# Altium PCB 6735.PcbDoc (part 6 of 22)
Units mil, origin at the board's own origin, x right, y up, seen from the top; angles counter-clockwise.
Board outline 2641.73 x 5165.35 mil, 6 copper layers (Top, Inner Layer 2, Inner Layer 3, Inner Layer 4, Inner Layer 5, Bottom), stack 35.7 mil thick; 1011 components, 790 nets, 4118 pads, 9325 vias.
Unrouted connection lines stored in the file: 4610.
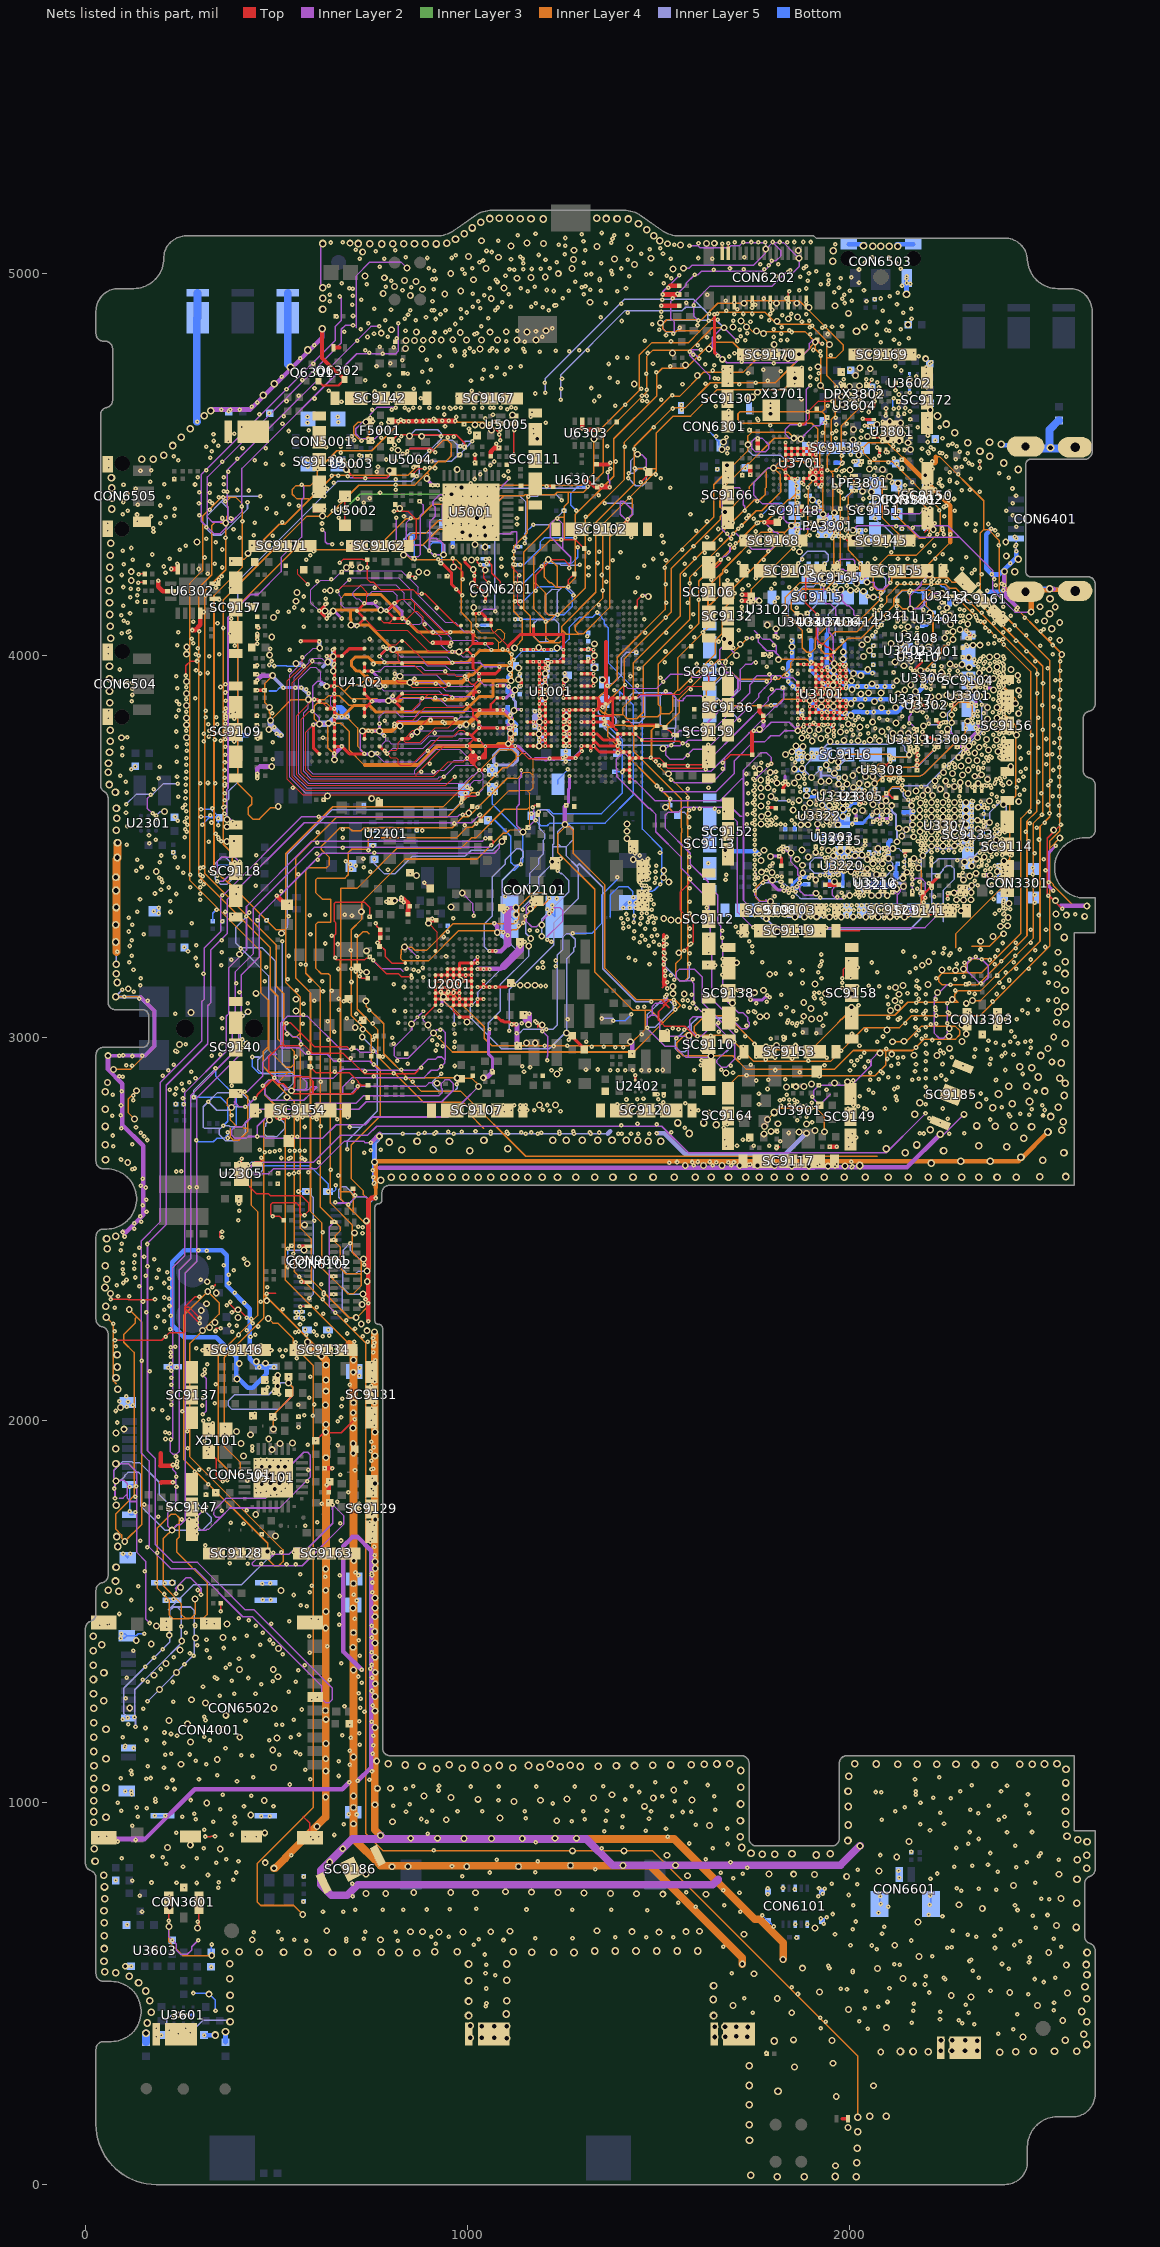
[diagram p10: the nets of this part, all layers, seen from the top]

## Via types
v1: diameter 12, hole 4, Top to Inner Layer 2, 3329 vias
v2: diameter 12, hole 4, Inner Layer 5 to Bottom, 3071 vias
v3: diameter 18, hole 10, Inner Layer 2 to Inner Layer 5, 1928 vias
v4: diameter 10, hole 4, Top to Inner Layer 2, 525 vias
v5: diameter 20, hole 12, Top to Bottom, 472 vias

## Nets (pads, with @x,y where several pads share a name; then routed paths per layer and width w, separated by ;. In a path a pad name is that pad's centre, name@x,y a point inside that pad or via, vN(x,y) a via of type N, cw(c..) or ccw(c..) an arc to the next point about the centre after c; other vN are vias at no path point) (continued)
D_GND: (continued)
  Top w4: v1(34.95,910.49) CON4001.14@36.94,912.47 ; v1(36.95,1463.49) 39.09,1465.62 CON4001.13@48.04,1465.62 ; CON4001.14@48.04,912.48 CON4001.14@36.94,912.47 ; CON4001.13@48.04,1470.55 CON4001.13@48.04,1465.63 ; v1(55.95,911.49) 54.96,912.47 CON4001.14@36.94,912.47 ; v1(56.95,1464.49) CON4001.13@55.81,1465.62 ; v1(58.63,4327.23) 58.63,4331.92 CON6505.4@58.9,4332.18 v1(58.9,4346.5) ; v1(59.33,3836.28) 59.33,3840.02 CON6504.4@58.9,3840.44 58.9,3854.01 v1(60.39,3855.49) ; v1(59.69,4022.38) 61.75,4020.32 58.9,4017.47 CON6504.5@58.9,4009.74 60,4008.64 v1(60,4005.68) ; v1(60.47,4491.79) 60.47,4499.91 CON6505.5@58.9,4501.48 58.9,4511.9 v1(60.65,4513.65) ; v1(65.95,2315.83) 111.1,2315.83 111.42,2315.52 180.82,2315.52 ; v1(77.31,2209.09) 199.72,2209.09 219.72,2229.09 254.81,2229.09 259.95,2231.22 259.95,2292.45 ; v1(135.95,4351.57) 145.81,4351.57 CON6505.1@147.48,4349.9 ; v1(137.95,4190.83) 138.95,4191.83 C6304.2@154.95,4191.83 ; v1(138.95,4212.83) 138.95,4213.83 C6306.2@154.95,4213.83 ; v1(155.95,4141.83) C6305.2@156.95,4140.83 ; v1(184.69,386.87) 184.69,393.23 ANT3608.1@184.95,393.49 v1(184.95,408.5) ; CON4001.11@211.42,1474.02 CON4001.11@211.42,1473.96 ; v1(211.57,743.46) CON3601.3@217.94,737.09 ; v1(212.95,1458.49) CON4001.11@212.95,1464.09 ; C6501.2@216.95,1770.83 217.82,1771.7 v1(220.6,1773.84) ; CON3601.3@217.94,743.81 217.94,743.46 CON3601.3@217.94,737.09 ; CON3601.3@217.94,745.16 217.94,743.84 219.3,745.19 217.94,745.19 217.94,755.94 v1(218.95,756.95) ; v1(219.29,403.47) 239.93,403.47 245.9,397.51 ANT3608.2@248.99,394.41 ; R6510.1@232.31,4462.09 v1(232.31,4463.09) ; v1@236.96,1545.49 v1@237.31,1545.5 ; v1(240.33,4240.97) 241.58,4239.72 U6302.13@241.58,4226.9 ; v1(242.8,394.41) ANT3608.2@248.99,394.41 ; CON3601.1@257.31,777.44 v1(258.38,776.37) ; v1(262.31,3948.09) 262.31,3958.92 262.36,3958.96 262.36,3973.83 274.6,3986.06 v1(291.94,3986.06) ; v1(262.85,409.49) 249.91,396.56 ANT3608.2@249.91,393.49 ; v1(274.43,396.62) 253.04,396.62 ANT3608.2@249.91,393.49 ; v1(293.82,1555.57) 302.31,1547.07 v1@302.31,1545.5 ; v1(294.31,687.09) v1@296.68,684.72 ; v1(294.7,752.8) 296.68,750.82 CON3601.4@296.68,737.09 ; v1(296.08,734.12) 296.08,736.49 CON3601.4@296.68,737.09 ; 296.68,677.09 v1@296.68,684.72 ; v1(298.31,2323.09) 287.21,2323.09 259.95,2295.83 ; v1(299.31,2253.09) 259.95,2292.45 ; v1(299.31,2267.09) 270.57,2295.83 259.95,2295.83 ; v1@302.33,1545.5 v1@302.94,1545.49 ; v1@313.97,910.5 327.56,910.5 ; C5120.1@315.31,1805.09 v1(315.31,1806.09) ; v1(316.95,1467.49) 317.05,1467.59 CON4001.19@327.57,1467.59 ; v1(321.31,1911.09) 321.31,1916.18 X5101.4@322.68,1917.54 ; v1(321.31,2182.09) 322.71,2183.49 SC9146.1@337.5,2183.49 ; v1(322.31,1966.09) X5101.3@322.31,1974.27 ; v1(324.31,1929.09) 324.31,1917.54 X5101.4@322.68,1917.54 ; v1(331.77,2348.16) 338.95,2351.83 338.95,2354.75 339.08,2354.89 ; SC9128.1@336.5,1651.49 v1(339.91,1651.49) 349.91,1651.49 v1(355.31,1646.09) ; v1(336.95,1467.49) CON4001.19@336.85,1467.59 ; v1(338.31,2182.68) SC9146.1@337.5,2183.49 ; v1(338.95,911.49) 328.55,911.49 ; U6302.8@339.02,4188.51 339.02,4189.14 U6302.8@339.02,4190.76 ; U6302.8@339.02,4188.51 U6302.8@339.02,4190.76 ; v1(339.85,4189.14) U6302.8@339.02,4190.76 ; v1(340.31,1811.09) C5119.1@341.31,1810.09 ; v1(340.31,2233.09) 340.31,2235.55 339.09,2236.77 342.4,2240.09 v1(354.31,2240.09) ; v1(351.91,2183.49) SC9146.1@337.5,2183.49 ; 353.95,1506.22 C6502.2@353.95,1520.83 ; v1(353.98,1499.57) 353.98,1506.19 ; v1(357.31,2478.09) 351.31,2478.09 351.31,2486.44 ; v1(357.31,2493.09) 351.36,2493.04 351.36,2486.49 ; v1(364.31,1964.09) X5101.2@364.31,1970.99 ; v1(365.31,1983.09) 367.95,1980.45 X5101.2@367.95,1974.63 ; v1(371.31,1843.09) 350.83,1843.09 342.31,1851.6 342.31,1897.91 ; v1(379.31,2309.09) 377.31,2307.09 377.31,2304.09 395.95,2285.45 395.95,2285.24 ; v1(383.31,2282.09) 386.46,2285.24 395.95,2285.24 ; v1(388.61,3515.22) 393.31,3510.52 SC9118.4@393.31,3501.45 ; v1(390.31,3460.09) 393.81,3456.59 393.31,3456.09 SC9118.3@393.31,3436.49 ; SC9140.4@393.31,3040.05 393.31,3042.78 410.06,3059.53 v1(411.62,3058.27) ; C2312.2@400.95,2579.49 v1(401.31,2579.09) ; v1(402.15,2673.61) 403.27,2671.33 U2305.7@407.95,2666.65 ; v1(409.3,2684.04) 409.3,2685.95 411.02,2685.95 411.02,2684.73 407.95,2681.65 U2305.7@407.95,2666.65 ; v1(410.62,2973.85) 409.38,2975.09 SC9140.3@393.31,2975.09 393.31,2979.14 v1(410.69,2996.52) ; v1(418.47,910.51) CON4001.18@433.86,910.51 ; v1(422.31,2268.09) 405.16,2285.24 395.95,2285.24 ; v1(433.95,2006.73) C5117.1@438.31,2011.09 ; C4101.2@434.95,4021.49 446.37,4032.9 449.02,4030.25 449.31,4029.96 v1(449.55,4030.77) ; v1(436.31,1932.09) 436.18,1931.95 U5101.24@436.18,1923.99 ; v1(443.11,2842.42) 449.48,2848.78 449.48,2851.36 v1(493.95,2895.83) ; R4103.1@444.95,3951.49 444.95,3951.83 v1(448.95,3951.83) ; v1(445.31,1881.09) 446.31,1878.09 462.3,1878.09 U5101.33@491.3,1849.09 ; v1(445.31,1895.09) 491.3,1855.09 U5101.33@491.3,1849.09 ; C4108.2@445.95,3930.49 445.95,3935.9 v1(449.65,3935.9) ; v1(446.51,910.51) CON4001.18@433.86,910.51 ; U2305.3@449.29,2670.08 458.08,2670.08 460.25,2672.25 v1(460.25,2686.52) ; C4102.2@449.95,4053.49 v1(449.95,4057.73) ; CON4001.18@450.31,915.09 433.86,915.09 CON4001.18@433.86,910.51 ; v1(450.95,3782.83) 449.95,3782.83 449.95,3788.47 C1103.2@452.81,3791.33 452.81,3793.63 v1(450.95,3795.49) ; v1(460.88,1700.95) 460.69,1701.37 460.35,1702.09 C5121.1@460.95,1701.49 ; C5105.1@469.31,2105.09 v1(474.31,2100.09) ; v1(474.61,2330.55) 477.23,2333.17 478.91,2331.49 497.54,2331.49 ; v1(484.31,1803.09) 484.31,1842.1 U5101.33@491.3,1849.09 ; v1(486.38,2013.23) C5115.1@490.31,2009.09 ; C5115.1@490.31,2009.09 v1(495.9,2003.53) ; v1(492.4,2075.4) 499,2075.4 C5104.2@499.31,2075.09 v1(506.31,2068.09) ; v1(493.4,2104.3) 494.19,2105.09 C5107.1@499.31,2105.09 ; v1(498.31,1854.09) 497.81,1854.59 U5101.33@491.81,1848.58 ; v1(500.31,1805.09) U5101.33@500.31,1840.08 ; R2310.2@502.95,2618.49 v1(503.31,2618.09) ; v1(503.31,2646.09) C2315.2@503.95,2645.49 ; v1(512.31,1814.09) U5101.33@512.31,1828.08 ; C6107.2@518.31,2523.09 508.31,2533.09 v1(490.31,2533.09) 484.66,2538.75 484.66,2563.92 489.83,2569.09 550.8,2569.09 560.44,2559.45 560.44,2542.35 566.47,2536.32 v1(573.19,2536.32) 583.84,2546.97 583.84,2568.54 565.33,2587.05 484.23,2587.05 478.79,2592.49 447.53,2592.49 429.28,2610.74 429.28,2611.35 407.95,2632.68 U2305.7@407.95,2644.49 U2305.7@407.95,2654.67 ; v1(522.31,1822.09) 518.3,1822.09 U5101.33@512.31,1828.08 ; v1(531.1,2791.95) 522.95,2787.83 499.89,2787.83 497.35,2790.37 ; C5112.1@531.31,2113.09 v1(532.31,2114.09) ; v1(532.31,1833.09) U5101.33@507.3,1833.09 ; v1(533.31,1862.09) 533.31,1861.09 503.3,1861.09 U5101.33@491.3,1849.09 ; v1(537.31,1849.09) 534.31,1846.09 U5101.33@494.3,1846.09 ; C6106.2@538.31,2456.09 v1(539.31,2456.09) ; C5116.1@557.31,2009.09 v1(558.31,2010.09) ; v1(562.31,2296.09) v1@563.98,2297.75 ; SC9154.3@562.31,2810.09 567.95,2804.45 v1(567.95,2792.83) ; 569.31,963.09 587.41,945 CON4001.15@587.41,907.94 ; v1(590.31,2922.92) 589.6,2924.34 588.85,2925.09 C6039.2@587.31,2925.09 595.31,2917.09 595.31,2916.6 602.83,2909.09 690.59,2909.09 714.05,2885.62 714.05,2883.33 721.29,2876.09 ; v1(590.97,1479.91) 587.41,1476.35 CON4001.16@587.41,1470.55 ; v1(592.14,1268.15) 599.66,1275.67 CON4001.6@601.19,1275.67 CON4001.6@605.77,1275.66 ; v1(594.37,2791.98) 595.87,2790.48 612.08,2806.7 615.46,2810.09 SC9154.4@625.21,2810.09 ; 597.31,4375.2 597.31,4377.2 611.31,4377.2 SC9139.5@611.31,4387.01 ; CON4001.6@601.19,1275.67 CON4001.6@605.77,1275.66 ; v1(601.95,1945.49) C5124.2@602.95,1946.49 623.55,1967.09 669.31,1967.09 v1(704.31,2002.09) ; v1(605.95,1275.49) CON4001.6@605.77,1275.66 ; v1(609.58,1478.97) CON4001.16@608.1,1477.49 ; v1(609.95,909.49) CON4001.15@589.34,909.49 ; CON4001.16@609.95,1477.49 CON4001.16@608.1,1477.49 ; v1(616.95,2801.83) SC9154.4@625.21,2810.09 ; SC9139.5@617.37,4389.52 613.83,4389.52 SC9139.5@611.31,4387.01 ; SC9139.5@618.15,4390.31 SC9139.5@614.62,4390.31 ; SC9139.5@619.59,4393.57 617.88,4393.57 SC9139.5@614.62,4390.31 ; v1(621.69,3623.09) 623.95,3623.09 C4106.2@623.95,3623.49 ; SC9154.4@627.27,2810.09 SC9154.4@627.28,2814.16 ; v1(628.03,2809.09) 628.03,2813.42 SC9154.4@627.28,2814.16 ; v1(638.8,1842.56) 633.35,1844.09 C5126.2@638.95,1838.49 ; v1(646.31,1779.09) 641.31,1784.09 C5122.2@639.3,1784.09 ; CON6102.30@649.55,2518.23 649.81,2518.49 v1(650.95,2518.49) ; v1(649.95,2423.49) CON6102.24@649.7,2423.73 ; v1(661.95,4382.49) 678.73,4382.49 ; v1(664.95,4242.83) 674.95,4252.83 724.95,4252.83 726.95,4250.83 C5015.1@736.95,4250.83 v1(736.95,4230.83) 736.95,4200.96 745.83,4192.09 753.31,4192.09 773.31,4172.09 857.95,4172.09 868.21,4161.83 v1(879.95,4161.83) 888.35,4161.83 964.64,4085.55 965.72,4085.55 972.55,4078.71 ; U5002.2@678.74,4341.12 678.73,4382.49 ; U5002.1@678.74,4417.1 678.73,4382.49 ; C2019.2@688.31,3102.09 690.95,3099.45 v1(690.95,3095.83) ; 689.55,2971.49 683.95,2977.09 599.31,2977.09 537.31,3039.09 525.95,3039.09 v1(525.95,3038.57) 517.31,3029.93 517.31,2981.09 515.31,2979.09 ; v1@689.75,1050.49 689.75,1052.28 v1(689.95,1052.49) ; C4001.2@689.95,1205.49 v1(691.95,1203.49) ; v1(692.95,4293.83) 704.16,4293.83 SC9162.3@710.5,4287.49 ; C9001.2@699.95,2605.49 703.53,2605.49 703.53,2588.09 v1(705.31,2588.09) ; R5128.2@704.95,1923.49 704.95,1926.72 R5128.2@705.31,1927.09 ; C2017.2@711.31,3185.09 719.95,3176.45 v1(719.95,3173.83) ; v1(716.44,1768.64) 711.59,1773.49 R5129.2@705.95,1773.49 713.13,1780.66 v1(716.81,1780.66) ; v1(717.95,3160.83) 722.69,3156.09 C2032.2@738.31,3156.09 ; v1(718.31,3042.09) 722.05,3045.83 C2018.2@725.95,3045.83 725.95,3047.83 v1(727.95,3049.83) ; C2044.2@722.31,2974.09 v1(724.59,2974.84) ; v1(727.95,4293.83) SC9162.3@716.84,4293.83 ; v1(735.95,4512.98) C5011.2@741.08,4518.11 741.08,4518.62 v1(744.95,4522.49) ; C6015.2@739.31,2876.09 721.29,2876.09 ; v1(740.46,4565.97) 745.38,4565.97 F5001.3@745.38,4562.52 ; v1(742.31,3317.09) C2034.2@743.31,3317.09 743.31,3341.9 730.13,3355.09 654.5,3355.09 650.88,3351.47 650.88,3305.31 654.31,3301.88 654.31,3271.29 650.88,3267.86 650.88,3208.7 654.5,3205.09 731.31,3205.09 734.06,3207.83 739.95,3207.83 739.95,3207.92 v1(743.79,3211.76) 743.89,3211.71 C2033.2@744.31,3211.47 ; v1(742.42,1768.37) 748.07,1768.37 SC9129.2@748.95,1767.49 ; C2033.2@743.35,3212.04 C2033.2@743.59,3212.04 ; C2033.2@743.59,3212.09 743.69,3212.09 C2033.2@743.95,3211.83 ; C2033.2@744.31,3215.13 744.31,3213.09 743.95,3212.72 C2033.2@743.95,3211.83 ; v1(745.11,4622.95) 745.11,4613.7 F5001.1@745.38,4613.7 ; SC9131.1@748.95,2007.04 SC9131.1@748.95,2007.73 ; SC9131.3@748.95,2125.94 749.31,2125.58 v1(749.31,2110.09) ; SC9131.1@750.89,2025.77 748.95,2023.83 748.95,2015.09 SC9131.1@748.95,2007.73 ; v1(750.95,4559.49) F5001.3@747.92,4562.52 ; v1(752.34,4613.2) F5001.1@745.38,4613.2 ; v1(752.95,4293.83) 763.61,4293.83 SC9162.2@769.95,4287.49 769.95,4290.83 v1(772.95,4293.83) ; v1(756.31,2015.09) SC9131.1@748.95,2007.73 ; v1(757.37,3005.22) 758.41,3004.19 759.31,3005.09 C2048.2@760.31,3005.09 ; v1(759.31,3300.09) 762.31,3300.09 762.31,3292.12 C2031.2@770.95,3283.49 ; C2036.2@767.31,2952.09 769.31,2954.09 773.31,2950.09 v1(778.31,2951.09) ; U4102.C10@769.3,4097.43 780.87,4085.86 793.33,4085.86 794.83,4085.86 806.08,4097.43 U4102.C12@808.67,4097.43 ; C2057.2@770.95,3262.49 769.31,3260.85 R2030.2@769.31,3239.09 774.8,3239.09 784.31,3229.58 784.31,3212.72 801.94,3195.09 835.98,3195.09 U2001.T5@836.84,3195.95 ; v1(794.31,3361.09) 798.31,3361.09 R2033.2@798.31,3358.09 ; v1(794.95,4610.49) F5001.7@798.16,4613.7 ; C5017.2@804.08,4482.11 787.06,4465.09 703.91,4465.09 686.26,4482.74 U5003.3@684.76,4482.74 ; v1(807.31,4377.97) 843.78,4377.97 865.31,4356.44 865.31,4308.09 SC9162.1@847.85,4290.62 ; C6031.2@809.31,4821.09 C6031.2@810.31,4821.09 ; v1(809.95,4295.83) 821.06,4295.83 SC9162.1@829.4,4287.49 ; v1(826.31,3360.09) 826.31,3363.49 C2041.2@826.95,3363.49 ; v1(830.62,4528.44) U5004.4@831.17,4529.71 ; U5004.4@835.97,4527.85 U5004.4@837.3,4527.86 U5004.4@837.3,4528.45 ; U5004.4@835.95,4527.88 835.95,4529.71 U5004.4@831.17,4529.71 ; U5004.4@837.3,4528.48 835.95,4529.83 U5004.4@831.17,4529.71 ; v1(841.89,4535.07) 848.91,4542.09 905.31,4542.09 v1(915.31,4532.09) ; C2020.2@848.95,3432.49 850.31,3432.49 v1(850.31,3429.09) ; v1(848.95,4214.83) 845.31,4211.19 C10082.2@845.31,4208.09 859.31,4208.09 v1(863.31,4204.09) ; U2001.R7@852.59,3164.45 848.23,3160.09 826.78,3160.09 818.78,3168.09 787.69,3168.09 C2033.2@744.31,3211.47 ; C5012.1@856.08,4472.11 856.08,4473.42 854.77,4473.42 870.18,4488.83 885.95,4488.83 v1(887.95,4490.83) ; v1(857.85,4493.42) 858.2,4493.08 U5004.1@861.48,4496.36 ; C10099.2@858.95,4254.83 v1(859.95,4254.83) ; v4(868.34,3211.7) 868.95,3211.08 U2001.P4@868.95,3210.99 ; v1(873.95,4403.98) C5009.1@874.08,4404.11 ; v1(878.02,2922.39) 861.72,2906.09 730.04,2906.09 695.04,2941.09 692.81,2941.09 673.81,2960.09 593.09,2960.09 574.09,2979.09 570.53,2979.09 564.87,2984.75 v1(563.95,2983.83) 559.21,2979.09 515.31,2979.09 ; v4(884.09,3054.22) 899.86,3069.99 U2001.L12@915.58,3085.71 ; v1(886.22,3406.42) 886.31,3406.47 C2016.2@901.95,3390.83 ; C2030.2@896.95,3308.49 C2030.2@896.95,3309.09 ; v1(906.95,3311.83) C2047.2@918.31,3308.09 ; v1(909.08,4446.11) U5001.1@912.88,4446.11 ; v4(915.58,3132.96) 915.45,3133.09 915.45,3134.96 U2001.L9@915.58,3135.09 ; v1(921.95,4446.49) U5001.1@913.53,4446.49 ; U2001.J9@947.09,3132.89 947.17,3132.59 U2001.J9@947.2,3132.48 ; U2001.J8@947.08,3148.4 U2001.J8@947.2,3148.4 ; U2001.J9@947.31,3131.09 947.25,3132.02 U2001.J9@947.23,3132.33 ; U2001.J9@947.31,3132.02 947.31,3132.72 U2001.J9@947.2,3132.83 ; SC9107.2@959.99,2810.09 967.95,2802.13 v1(967.95,2799.17) ; v1(961.11,4254.46) 961.95,4254.46 961.95,4243.93 986.95,4218.93 v1(986.95,4200.49) ; U2001.H12@962.83,3085.71 962.83,3069.96 U2001.G14@978.57,3054.22 ; v1(966.95,4305.49) 966.95,4340.8 1001.26,4375.11 U5001.41@1009.08,4375.11 1027.33,4375.11 v1(1042.95,4359.49) ; v4(978.57,3101.46) U2001.G11@978.57,3101.83 ; v1@981.61,4647.49 v1(982.23,4649) ; U1001.A27@982.73,4078.72 972.55,4078.71 ; U1001.A27@982.73,4078.72 972.55,4078.71 ; C10098.2@986.31,3627.09 986.31,3628.09 990.31,3632.09 1020.31,3632.09 1026.75,3638.52 v1(1026.54,3638.72) ; v1(987.42,3583.34) 989.65,3586.3 990.38,3586.33 992.01,3584.7 999.42,3592.12 999.42,3592.96 R1101.2@1011.95,3605.49 ; L5009.2@992.31,4546.09 992.31,4556.12 970.34,4578.09 817.02,4578.09 800.28,4561.35 F5001.5@798.52,4561.35 ; v4(998.48,3873.99) 1014.36,3858.11 1014.62,3858.11 1015.62,3857.11 ; v4(998.48,3936.99) 1010.36,3925.11 1018.1,3925.11 ; U1001.B23@998.48,4015.73 1014.23,4031.47 ; 1002.11,3735.89 1006.88,3735.89 1006.88,3731.25 ; 1006.88,3737.01 1012.72,3731.17 ; v4(1010.07,3164.45) 1009.95,3164.33 1009.95,3164.45 1009.95,3165.09 U2001.E7@1010.07,3164.97 ; v1@1012.94,3315.84 v1@1016.33,3319.23 ; 1013.85,3716.89 1018.96,3711.78 ; 1013.84,3718.77 1013.84,3728.92 1013.84,3730.05 ; U1001.C6@1014.23,3748.01 1014.23,3747.47 1014.23,3742.99 1014.23,3737.03 1014.23,3735.34 1012.72,3733.84 1012.72,3731.17 ; 1014.23,3968.48 v4(1029.98,3952.73) ; 1018.96,3723.88 1018.96,3711.78 ; 1019.08,4515.36 1020.08,4514.36 L5010.2@1020.08,4504.7 ; 1019.46,3905.48 1018.1,3906.84 1018.1,3925.11 ; v1(1025.14,4253.35) 1025.14,4244.55 1041.58,4228.11 1041.58,4203.86 v1(1054.95,4190.49) ; U2001.D6@1025.95,3180.49 U2001.D6@1025.82,3181.35 ; v4(1029.98,3700.77) 1018.96,3711.78 ; v4(1029.98,3936.99) 1018.1,3925.11 ; v1(1032.3,3583.61) 1032.8,3579.71 1032.95,3579.83 1034.95,3577.83 C10091.2@1034.95,3567.83 ; U1001.E31@1045.76,4141.75 U1001.E31@1046.08,4142.07 ; v1(1056.95,4253.49) 1056.95,4243.49 1062.95,4237.49 1062.95,4215.97 1084.95,4193.97 v1(1084.95,4180.49) ; U2001.B3@1057.13,3227.49 v4(1057.32,3227.44) ; v4(1057.32,3132.96) U2001.B9@1057.31,3133.08 ; v1(1058.24,4606.51) 1058.46,4606.73 L5007.2@1059.06,4607.34 ; C10089.2@1058.95,3522.83 1066.37,3515.42 1066.37,3506.92 1064.86,3506.92 1064.45,3506.73 v1(1062.02,3504.03) ; L5007.2@1059.08,4607.32 L5007.2@1059.08,4606.11 1060.31,4604.88 1060.31,4603.09 1061.8,4603.09 1084.95,4579.94 v1(1084.95,4563.49) ; v1(1064.39,2913.67) 1064.39,2910.65 C2043.2@1065.81,2910.65 ; U2001.A3@1073.05,3227.21 v4(1073.06,3227.44) ; v1(1079.42,4607.18) 1079.42,4607.49 1086.48,4607.49 U5005.5@1086.86,4607.11 ; v1(1081.35,4544.09) L5006.2@1081.95,4543.49 ; C2015.2@1084.88,3333.06 1084.88,3340.49 C2015.2@1089.45,3340.49 ; v1(1093.95,3330.83) 1090.39,3332.09 1090.31,3339.62 C2015.2@1089.45,3340.49 ; v1(1093.95,4607.49) U5005.5@1087.24,4607.49 ; C10088.2@1094.59,3521.88 1094.95,3523.83 C10088.2@1096.95,3523.83 ; C2015.2@1098.31,3333.09 1097.95,3332.72 C2015.2@1090.18,3340.49 ; v1(1102.95,3338.83) 1102.3,3336.99 1102.12,3333.02 1100.07,3333.11 1100.07,3340.49 C2015.2@1090.18,3340.49 ; C2011.2@1114.95,3150.49 C2011.2@1112.95,3148.49 ; v1(1120.95,4525.49) U5005.2@1120.95,4606.75 ; v1(1121.95,3138.83) 1121.95,3143.83 C2011.2@1112.95,3143.83 ; v1(1136.62,2975.18) 1136.42,2974.98 C2013.2@1132.31,2979.09 ; v1(1136.95,3239.83) v1(1136.95,3251.83) ; U1001.L3@1139.95,3700.5 v4(1140.21,3700.77) ; v1(1148.95,3063.83) 1145.95,3060.83 C2012.2@1145.95,3059.83 1157.95,3059.83 1159.95,3061.83 v1(1161.42,3063.51) ; C10095.2@1157.95,3550.49 1157.95,3550.72 1158.76,3551.53 1158.87,3551.42 v1(1160.01,3550.29) ; v1(1169.95,3603.49) 1175.29,3608.83 R1227.2@1184.95,3608.83 ; SC9111.2@1169.95,4604.83 1176.95,4597.83 SC9111.2@1176.95,4594.45 ; v1(1171.51,4593.7) 1174.6,4596.8 SC9111.2@1176.95,4594.45 ; v1(1172.79,4580.32) 1176.08,4580.32 SC9111.2@1176.95,4579.45 SC9111.2@1176.95,4594.45 ; SC9111.1@1176.95,4634.57 SC9111.1@1174.43,4637.09 ; v1(1178.31,4170.09) 1178.31,4211.31 1218.49,4251.49 1251.92,4251.49 1265.89,4237.51 v1(1265.89,4229.49) ; v1(1180.95,3039.83) 1179.09,3039.83 1180.02,3038.9 v1@1183.96,3034.97 ; 1183.9,3032.41 1183.95,3032.41 ; 1183.95,3027.99 1183.95,3032.41 ; v1@1183.95,3034.96 1183.95,3032.41 ; v1(1194.95,3017.83) 1199.52,3017.83 1184.94,3032.41 ; v1(1207.31,4443.09) 1214.35,4443.09 1214.95,4442.49 C6315.2@1223.95,4442.49 ; v1(1208.31,3257.09) 1207.93,3257.97 1208.56,3257.34 1215.17,3250.72 v1@1215.17,3249.15 ; v1(1213.14,3325.5) 1219.13,3327.36 1219.07,3328.97 ; v4(1214.29,3730.78) 1159.31,3730.78 1134.6,3755.49 1132.73,3755.49 ; v1(1219.25,3251.41) 1218.95,3252.83 v1@1218.85,3252.83 ; C2039.2@1228.9,3457.09 1228.91,3457.93 C2039.2@1228.91,3459.55 ; v1(1236.41,3457.9) 1237.96,3457.91 1237.95,3459.55 C2039.2@1228.91,3459.55 ; v1(1242.91,3468.38) 1228.91,3468.38 C2039.2@1228.91,3459.55 ; v1(1244.95,4302.83) 1282.61,4302.83 C10084.2@1304.95,4280.49 ; v1(1264.88,2995.61) 1264.04,2999.97 1270.31,3004.09 1271.31,3005.09 C2055.2@1273.95,3005.09 ; v4(1266.2,3685.02) U1001.W2@1266.13,3685.04 ; C10093.2@1278.95,4213.83 1270.95,4205.83 1270.46,4205.83 1262.95,4198.32 v1(1262.95,4179.83) ; SC9102.3@1350.95,4330.49 SC9102.3@1359.29,4338.83 ; SC9102.3@1369.82,4341.15 1369.1,4341.19 1368.95,4338.83 SC9102.3@1368.49,4338.83 ; v1(1369.94,4336.63) SC9102.3@1368.49,4338.83 ; U1001.AH11@1407.93,3826.75 1423.68,3826.75 U1001.AK10@1439.43,3811 1449.51,3821.09 1492.3,3821.09 C1104.2@1496.3,3817.09 ; U1001.AH15@1407.93,3889.74 1407.93,3919.5 v4(1411.9,3923.47) ; SC9102.4@1415.91,4330.49 1418.57,4330.49 v1(1418.57,4356.75) ; v1(1425,3501.11) 1425.75,3503.74 1426.11,3504.99 1427.48,3502.46 C10040.2@1428.92,3499.8 ; v1(1425.31,3487.09) 1423.31,3489.09 1423.31,3491.26 C10040.2@1433.54,3501.49 ; C2412.2@1429.31,2958.09 v1(1430.31,2958.09) ; C10040.2@1432.45,3497.24 1435.54,3495.86 C10040.2@1436.01,3495.62 ; v1(1436.01,3495.15) C10040.2@1436.01,3495.62 ; U1001.AK9@1439.43,3795.25 U1001.AL8@1455.17,3779.51 1458.59,3776.09 1554.31,3776.09 1560.81,3769.59 v1(1562.31,3771.09) ; v1(1447.95,3429.49) 1456.95,3437.49 C10036.2@1458.4,3437.49 ; v1(1447.95,3449.49) C10036.2@1458.4,3439.04 ; v1(1448.95,3359.49) 1449.95,3360.49 C10038.2@1458.4,3360.49 ; v1(1448.95,3379.49) C10038.2@1458.4,3370.04 ; v1(1453.09,4454.09) 1473.95,4474.94 NTC6301.2@1473.95,4480.49 1465.35,4489.09 v1(1464.31,4489.09) ; U1001.AL5@1455.17,3732.26 1479.31,3732.26 1501.99,3732.26 1520.16,3714.09 SC9159.4@1619.95,3714.09 ; v1(1457.52,4156.53) 1457.52,4159.09 1457.11,4159.09 1450.65,4152.63 1444.25,4146.23 1443.79,4145.77 1443.79,4135.41 1444.08,4135.12 1444.08,4128.73 U1001.AK30@1441.31,4125.96 ; v1(1459.95,3449.49) 1458.4,3440.49 C10036.2@1458.4,3439.04 ; v1(1460.95,3429.49) 1460.95,3429.94 C10036.2@1458.4,3437.49 ; v1(1463.95,3360.49) C10038.2@1458.4,3360.49 ; v1(1464.95,3379.49) 1458.4,3372.94 C10038.2@1458.4,3370.04 ; v1(1500.71,3713.71) 1501.72,3714.72 1502.35,3714.09 C10078.2@1515.3,3714.09 1523.3,3706.09 1613.32,3706.09 1628.84,3721.6 SC9159.4@1630.95,3723.71 ; 1509.31,3098.09 1516.91,3090.5 1516.91,3088.68 ; 1509.31,3131.09 1516.31,3138.09 1516.9,3138.09 ; 1512.31,3086.09 1516.91,3086.09 ; C2007.2@1514.9,3005.09 1514.91,3011.79 v1(1521.95,3018.83) ; C10090.2@1516.3,3812.09 1522.89,3805.5 1524.55,3805.5 1525.96,3804.09 1527.31,3804.09 v1(1538.31,3793.09) ; v1(1516.96,3162.51) 1518.09,3162.9 1518.09,3144.31 v1@1519.31,3143.09 ; v1(1522.31,3130.09) 1521.31,3130.09 1521.31,3133.68 1516.91,3138.09 ; 1527.31,3079.09 1518.31,3088.09 1516.91,3088.09 ; 1527.31,3096.09 1525.31,3097.09 1516.91,3088.68 ; v1(1566.69,3227.59) 1566.69,3228.22 v1@1584.31,3245.85 ; v1(1582.83,3414.96) 1581.72,3411.86 1578.95,3411.83 1578.95,3403.73 1571.31,3396.09 1571.06,3396.09 1555.79,3380.82 1555.79,3334.5 1570.21,3320.09 1583.28,3320.09 1587.31,3316.06 1590.31,3313.04 1590.31,3251.85 v1@1584.31,3245.85 ; v1(1584.31,3246.09) v1@1584.31,3245.85 ; v1(1601.31,3004.09) 1600.31,3003.09 1595.81,3003.09 1567.81,3031.09 1514.81,3031.09 1499.31,3046.59 1499.31,3068.49 1516.91,3086.09 ; v1(1615.81,3819.33) 1615.81,3800.49 SC9159.3@1630.31,3800.49 ; v1(1620.95,3891.6) 1620.95,3889.83 1630.31,3880.47 SC9159.2@1630.31,3865.45 ; v1(1624.15,3956.09) 1624.15,3953.62 1625.93,3951.83 1628.31,3949.49 1628.31,3947.09 1630.31,3945.09 SC9159.1@1630.31,3920.57 ; v1(1624.31,3726.13) 1624.31,3729.53 SC9159.4@1630.31,3735.53 ; v1(1626.79,3311.09) SC9112.3@1630.31,3311.09 ; SC9112.2@1628.74,3354.48 1626.31,3356.09 SC9112.2@1626.31,3372.05 ; SC9112.4@1630.31,3246.13 1630.31,3263.09 1629.31,3264.09 v1(1630.31,3264.09) ; SC9106.4@1630.31,4231.45 1650.37,4231.45 1662.31,4243.39 v1(1662.31,4251.39) ; SC9159.4@1642.31,3726.09 1632.87,3735.53 SC9159.4@1630.31,3735.53 ; CON6202.30@1665.72,5053.06 CON6202.30@1665.31,5059.09 ; v1(1666.31,3165.28) SC9138.2@1682.95,3181.92 ; v1(1666.59,3238.74) 1681.26,3238.74 SC9138.1@1681.43,3238.56 ; v1(1667.05,3720.35) 1687.78,3741.09 R3102.2@1744.15,3741.09 ; v1(1667.31,3115.56) 1668.71,3116.96 SC9138.3@1682.95,3116.96 v1(1680.18,3122.5) 1682.95,3119.92 v1(1667.31,3135.56) ; v1(1667.31,3189.56) 1675.31,3189.56 SC9138.2@1682.95,3181.92 ; v1(1667.31,3206.56) 1682.95,3190.92 SC9138.2@1682.95,3181.92 ; v1(1669.55,3880.98) 1670.24,3881.67 1675.76,3876.14 1675.76,3864.09 SC9136.2@1681.31,3864.09 1690.95,3854.45 1690.95,3848.83 SC9136.2@1691.21,3849.09 ; SC9130.3@1679.31,4731.54 1679.31,4747.09 v1(1687.31,4755.09) ; SC9166.1@1680.82,4360.64 1683.31,4358.15 v1(1683.31,4352.09) ; SC9166.3@1680.82,4479.54 1681.31,4479.54 v1(1681.31,4465.09) ; v1(1681.31,5079.09) 1680.31,5058.09 1681.46,5056.94 CON6202.28@1681.46,5051.05 ; CON6202.25@1697.21,4923.98 v1(1697.31,4924.09) ; v1(1706.68,3125.13) 1709.31,3124.56 1710.05,3125.3 v1(1719.95,3125.3) v1@1720.95,3125.3 ; v1(1716.31,3267.56) 1716.31,3273.64 SC9119.1@1723.23,3280.56 ; R3719.1@1717.95,4472.49 1718.24,4472.6 v1(1718.2,4472.72) ; SC9119.1@1727.31,3289.56 1723.24,3285.48 SC9119.1@1723.23,3280.56 ; v1(1728.31,4306.09) 1735.86,4306.09 SC9168.1@1740.86,4301.09 ; v1(1729.31,4677.09) 1737.06,4676.79 C3706.2@1739.31,4676.09 ; SC9119.1@1731.31,3276.56 1727.31,3280.56 SC9119.1@1723.23,3280.56 ; v1(1736.95,4590.49) R3718.1@1737.95,4589.49 ; v1(1743.92,4909.83) 1744.46,4909.83 1744.95,4909.83 1744.95,4921.42 CON6202.19@1744.46,4923.92 v1(1744.31,4925.09) ; R3732.2@1756.66,4542.8 1756.95,4543.49 R3732.2@1758.95,4543.49 ; SC9119.2@1762.31,3270.56 1772.31,3280.56 SC9119.2@1778.35,3280.56 ; SC9103.2@1765.93,3331.38 1775.29,3331.38 SC9103.2@1778.46,3334.56 ; v1(1772.31,2957.56) SC9153.2@1778.35,2963.56 ; v1@1773.15,3830.33 1774.12,3829.37 1774.12,3828.76 v1(1773.9,3828.76) ; SC9153.2@1778.35,2963.56 1780.35,2965.56 v1(1794.31,2965.56) ; SC9103.2@1780.31,3332.71 SC9103.2@1779.53,3333.49 ; v1(1781.31,344.09) 1782.31,343.09 C6012.2@1782.31,342.09 ; v1(1790.59,3275.64) 1790.65,3275.64 1790.65,3285.08 1792.18,3286.6 1792.18,3288.73 SC9119.2@1789.35,3291.56 ; v1(1791.31,4924.09) CON6202.13@1791.7,4923.7 ; v1(1792.31,4660.09) X3701.2@1794.45,4657.95 ; C3109.2@1803.65,4050.59 1803.65,4050.69 v1(1805.74,4050.69) ; v1(1807.96,2712.06) 1807.84,2712.25 1809.17,2713.11 1815.08,2714.58 1816.29,2714.58 ; v1(1827.03,2994.91) C3291.2@1829.08,3000.58 ; v1(1827.53,3272.77) 1829.53,3270.78 1839.31,3280.56 SC9119.3@1843.31,3280.56 1853.31,3270.56 1861.31,3270.56 1861.81,3271.57 v1(1863.12,3274.29) ; U3701.H7@1831.32,4480.09 v4(1831.94,4479.47) ; v1(1839.31,4923.09) 1838.94,4922.71 CON6202.7@1838.94,4923.92 1838.94,4951.82 v1(1840.95,4953.83) ; v1(1856.31,4711.09) 1856.31,4727.66 X3701.4@1857.45,4728.8 1857.45,4740.96 v1(1856.31,4742.09) ; U3101.L14@1863.66,3804.1 v4(1879.41,3819.85) ; v1(1868.31,4604.09) 1878.04,4604.09 1893.31,4619.37 1893.31,4641.68 1917.72,4666.09 v1(1954.31,4666.09) ; v1(1868.41,4050.23) 1868.41,4050.35 C3108.1@1868.65,4050.59 ; v1(1875.42,4368.16) 1875.59,4368.24 1875.98,4368.42 R3701.1@1875.5,4368.42 ; SC9105.2@1900.65,4215.59 1891.65,4215.59 1884.65,4208.59 1884.65,4137.69 v1(1914.67,4107.68) 1913.65,4107.68 1913.65,4083.09 1911.65,4081.09 1911.65,4044.1 1922.75,4033.01 1928.63,4033.01 1939.47,4022.17 1944.81,4022.17 U3101.E1@1958.15,4008.83 U3101.F2@1942.4,3993.08 U3101.E3@1958.15,3977.33 ; v1(1902.31,3280.56) SC9119.4@1908.27,3280.56 ; U3701.C9@1910.57,4448.09 v4(1910.68,4447.97) ; C6206.2@1914.31,4826.09 1923.99,4816.42 v1(1927.49,4816.42) ; C3916.2@1919.08,2876.58 1919.46,2876.58 v1(1919.46,2876.26) ; C3914.2@1921.08,2823.58 v1(1921.08,2824.58) ; v1(1924.18,3273.68) 1908.27,3273.68 SC9119.4@1908.27,3280.56 ; U3701.B9@1926.31,4448.09 v4(1926.43,4447.97) ; v1(1937.8,3288.09) 1937.8,3290.21 1937.6,3290.41 1934.31,3290.56 1918.27,3290.56 SC9119.4@1908.27,3280.56 ; v1@1940.63,4216.91 v1(1940.65,4218.59) ; C3710.2@1941.17,4623.13 1941.17,4623.94 v1(1941.31,4624.09) ; C3915.2@1947.31,2715.56 v1(1947.51,2715.6) ; SC9119.5@1963.39,3280.56 1963.39,3285.64 1964.31,3286.56 1966.31,3286.56 SC9119.5@1965.31,3287.56 ; SC9119.5@1964.03,3280.96 2026.28,3280.96 ; v1(1975.99,4712.26) 1977.06,4710.23 1981.55,4710.23 DPX3802.7@1981.56,4707.8 ; L3816.2@1977.31,4742.09 v1(1981.31,4742.09) ; v1(1979.94,3156.31) 1982.31,3156.56 1982.31,3179 1985.24,3181.92 SC9158.4@2004.95,3181.92 ; v1(1985.31,4308.09) 1992.31,4301.09 SC9145.1@2023.86,4301.09 ; v4(1989.64,3835.6) v4(1989.64,3851.35) 1988.18,3851.35 1988.18,3863.14 v4(1989.64,3867.09) ; v1(2004.57,4469.98) 2010.31,4471.09 LPF3801.1@2010.58,4470.78 LPF3801.1@2010.58,4470.78 LPF3801.1@2010.58,4470.78 ; v1(2009.31,4684.09) 2012.35,4684.09 DPX3802.9@2012.95,4683.49 ; v1(2009.31,4798.09) 2015.26,4798.09 SC9169.1@2025.78,4787.57 ; LPF3801.2@2010.58,4451.09 v1(2011.31,4451.09) ; v1(2011.61,4666.1) DPX3802.2@2011.61,4659.18 ; v1(2015.66,3570.49) L3332.1@2015.65,3570.59 ; v1(2019.31,4655.09) DPX3802.2@2015.23,4659.18 ; v1(2024.31,4799.09) 2025.78,4797.62 SC9169.1@2025.78,4787.57 ; v1(2037.52,4450.71) 2042.31,4451.09 LPF3801.5@2044.05,4451.09 v1(2051.31,4451.09) ; v1(2040.31,4798.09) 2036.3,4798.09 SC9169.1@2025.78,4787.57 ; v1(2042.31,4723.09) 2042.31,4707.8 DPX3802.5@2044.35,4707.8 ; v1(2049.05,4637.64) 2050.36,4636.33 2056.72,4642.69 2057.17,4642.69 2064.47,4649.99 2064.47,4651.26 2064.72,4651.26 2064.72,4665.76 v1(2064.97,4665.76) ; v1(2057.31,4722.09) 2057.31,4719.98 2045.87,4708.53 DPX3802.5@2045.14,4707.8 ; L3218.1@2060.65,3470.59 v1(2061.91,3470.62) ; U3801.9@2063.06,4570.34 2094.55,4570.34 U3801.21@2110.3,4586.09 2110.3,4588.1 v1(2086.31,4612.09) ; v1(2066.31,4799.09) 2073.71,4799.09 SC9169.2@2085.23,4787.57 2087.75,4790.09 v1(2090.31,4790.09) ; U3308.2@2075.81,3700.59 U3308.2@2082.58,3700.59 ; v1(2085.65,3700.59) U3308.2@2082.58,3700.59 ; v1(2094.37,4627.64) 2094.37,4633.33 U3801.4@2094.55,4633.33 ; v1(2094.49,4646.75) v1(2094.49,4646.75) v1@2094.55,4641.85 ; v1(2101.65,3676.59) U3308.5@2105.34,3675 ; U3308.7@2105.58,3723.59 2105.58,3726.18 U3308.7@2105.34,3726.18 U3308.7@2105.57,3723.58 ; v1(2105.65,3722.59) U3308.7@2105.57,3723.58 ; v1(2110.5,3380.59) C3264.2@2110.65,3380.59 ; v1(2119.31,4694.09) L3821.2@2119.31,4714.09 ; DIPX3801.2@2125.3,4407.09 DIPX3801.2@2125.6,4406.79 ; v1(2126.8,4627.43) U3801.2@2126.8,4633.33 ; C3806.2@2127.31,4665.09 v1(2127.72,4665.07) ; L3315.2@2130.65,3680.59 2130.65,3674.59 v1(2138.65,3674.59) ; v1(2131.31,4798.09) 2134.16,4798.09 SC9169.3@2144.68,4787.57 v1(2148.83,4787.57) ; C3805.2@2135.35,4488.58 C3805.2@2135.31,4489.09 C3805.2@2135.31,4489.09 2135.31,4490.09 v1(2136.31,4491.09) ; U3801.1@2141.68,4633.47 2141.8,4633.58 v1(2141.8,4633.33) ; v1(2143.08,4538.11) U3801.15@2142.34,4538.84 ; U3313.2@2145.81,3780.59 2151.34,3780.59 2175.34,3804.59 v1(2175.34,3806.18) ; U3313.4@2155.65,3755 2155.65,3756.08 v1(2158.08,3756.08) ; U3801.17@2157.29,4571.09 U3801.17@2157.54,4570.83 ; v1(2158.3,4619.09) U3801.20@2157.54,4618.33 ; v1(2159.31,4432.09) DIPX3801.4@2159.06,4431.83 ; v1(2164.65,3322.59) v1(2177.65,3322.59) v1(2230.65,3322.59) ; U3306.7@2167.06,3960.28 2167.64,3960.85 2169.14,3959.35 2191.78,3936.71 2192.65,3935.84 U3306.2@2192.65,3930.75 ; U3313.5@2175.34,3755 2175.34,3756.58 v1(2177.48,3756.58) ; 2195.31,4323.09 SC9150.3@2202.95,4330.72 ; U3309.5@2230.06,3760.9 v1(2231.65,3760.59) ; SC9185.1@2236.22,2777.19 v1(2236.22,2778.49) ; U3309.2@2255.65,3790.43 v1(2255.65,3793.31) ; v1(2260.37,2838.9) 2260.37,2845.4 SC9185.2@2266.08,2851.11 2266.08,2857.66 v1(2269.55,2861.13) ; v1(2265.65,3870.59) 2274.65,3879.59 2275.43,3879.59 2291.43,3895.59 v1(2300.81,3895.59) ; SC9185.3@2295.95,2925.03 v1(2295.95,2927.15) ; v1(2302.82,3140.29) 2304.1,3140.29 L3317.2@2304.3,3140.09 ; v1(2339.31,4491.09) 2339.31,4496.28 v1(2339.31,4509.09) ; L3346.2@2385.3,3163.09 2385.71,3163.5 v1(2386.06,3163.5) ; v5@2522.07,4168.58 2522.99,4169.49 v5(2523.05,4175.08) ; v1(2552.3,3558.09) 2516.31,3522.1 2516.31,3377.09 v1(2555.31,3338.09) ; CON4001.13@48.04,1465.62 CON4001.13@55.81,1465.62 ; CON4001.13@48.04,1465.63 CON4001.13@55.81,1465.62 ; CON4001.11@211.42,1465.63 CON4001.11@212.95,1464.09 ; CON4001.11@211.42,1465.63 CON4001.11@212.95,1464.09 ; CON4001.11@211.42,1465.63 CON4001.11@211.42,1473.96 ; CON4001.11@211.42,1465.63 CON4001.11@211.42,1473.96 ; v1@217.94,690.46 v1(218.31,690.09) 217.94,689.72 217.94,690.09 v1@217.94,690.46 ; v1@217.94,690.46 CON3601.3@217.94,737.09 ; ANT3608.2@248.99,394.41 ANT3608.2@249.91,393.49 ; 259.95,2292.45 259.95,2295.83 ; v1@296.68,684.72 296.68,687.09 296.68,734.12 CON3601.4@296.68,737.09 ; v1@302.31,1545.49 v1(302.31,1543.09) v1@302.94,1545.49 ; v1@302.31,1545.49 v1@302.94,1545.49 ; X5101.3@322.31,1974.27 X5101.3@322.68,1974.63 X5101.3@322.68,1981.72 ; X5101.3@322.31,1974.27 X5101.3@322.68,1974.63 X5101.3@322.68,1981.72 ; X5101.4@322.68,1917.54 325.22,1915 342.31,1897.91 ; X5101.4@322.68,1917.54 342.31,1897.91 ; X5101.3@322.68,1981.72 v1(322.31,1982.09) 322.68,1982.45 X5101.3@322.68,1981.72 ; 327.57,910.51 328.55,911.49 ; 327.56,910.5 328.55,911.49 ; CON4001.19@327.57,1467.59 CON4001.19@336.85,1467.59 ; CON4001.19@327.57,1467.59 CON4001.19@336.85,1467.59 ; 351.31,2486.44 351.36,2486.49 ; 351.31,2486.44 351.36,2486.49 ; X5101.2@364.31,1970.99 X5101.2@367.95,1974.63 ; X5101.2@364.31,1970.99 X5101.2@367.95,1974.63 ; U2305.7@404.51,2658.52 404.1,2658.52 U2305.7@407.95,2654.67 ; U2305.7@404.51,2658.52 U2305.7@404.71,2658.52 ; U2305.7@404.51,2658.52 404.49,2658.15 405.87,2657.82 U2305.7@407.95,2655.74 ; U2305.7@404.51,2658.52 v1(404.61,2661.22) U2305.7@404.71,2658.52 ; U2305.7@404.71,2658.52 407.72,2658.52 U2305.7@407.95,2658.28 ; U2305.7@404.71,2658.52 404.73,2658.16 407.42,2658.26 U2305.7@407.95,2658.28 ; U2305.7@407.95,2654.67 U2305.7@407.95,2655.74 ; U2305.7@407.95,2655.74 U2305.7@407.95,2658.28 ; U2305.7@407.95,2658.28 407.95,2661.22 U2305.7@407.95,2666.65 ; CON4001.18@433.86,910.51 CON4001.18@433.86,910.51 CON4001.18@433.86,910.51 ; U5101.24@436.18,1923.99 U5101.24@436.31,1923.86 ; U5101.24@436.18,1923.99 U5101.24@436.31,1923.86 ; U5101.24@436.18,1923.99 v1(436.31,1920.09) U5101.24@436.31,1923.86 ; C4116.2@445.31,3909.39 C4116.2@445.41,3909.83 ; C4116.2@445.31,3909.39 C4116.2@445.55,3909.41 ; C4116.2@445.31,3909.39 C4116.2@445.31,3909.83 ; C4116.2@445.31,3909.39 C4116.2@445.55,3909.42 ; C4116.2@445.31,3909.39 C4116.2@445.56,3909.39 ; C4116.2@445.31,3909.39 C4116.2@445.55,3909.41 ; C4116.2@445.31,3909.83 445.31,3910.13 C4116.2@445.41,3909.83 ; C4116.2@445.31,3909.83 C4116.2@445.41,3909.83 ; C4116.2@445.41,3909.83 v1(448.95,3909.83) ; C4116.2@445.41,3909.83 C4116.2@445.53,3909.46 ; C4116.2@445.56,3909.39 445.72,3908.9 445.77,3908.95 C4116.2@446.19,3909.39 ; C4116.2@445.56,3909.39 C4116.2@446.28,3909.48 ; C4116.2@445.56,3909.39 C4116.2@446.19,3909.39 ; C4116.2@445.55,3909.41 C4116.2@445.63,3909.42 ; C4116.2@445.56,3909.39 C4116.2@445.98,3909.45 ; C4116.2@445.55,3909.41 C4116.2@445.63,3909.42 ; C4116.2@445.55,3909.41 C4116.2@445.63,3909.42 ; C4116.2@445.55,3909.42 C4116.2@446.09,3909.48 ; C4116.2@445.53,3909.46 C4116.2@445.55,3909.42 ; C4116.2@445.63,3909.42 C4116.2@446.09,3909.48 ; C4116.2@445.63,3909.42 C4116.2@446.12,3909.48 ; C4116.2@445.63,3909.42 C4116.2@445.98,3909.45 ; C4116.2@445.98,3909.45 C4116.2@446.3,3909.5 ; C4116.2@445.98,3909.45 446.19,3909.47 C4116.2@446.28,3909.48 ; C4116.2@446.12,3909.48 C4116.2@446.3,3909.5 ; C4116.2@446.09,3909.48 v1(448.95,3909.83) ; C4116.2@446.19,3909.39 C4116.2@446.28,3909.48 ; C4116.2@446.19,3909.39 v1(448.95,3909.83) ; C4116.2@446.3,3909.5 v1(448.95,3909.83) ; C4116.2@446.28,3909.48 v1(448.95,3909.83) ; U5101.33@491.3,1849.09 491.3,1848.58 U5101.33@491.8,1848.58 ; U5101.33@491.3,1849.09 U5101.33@491.81,1848.58 ; U5101.33@491.81,1848.58 U5101.33@494.3,1846.09 ; v1(493.95,2895.83) 493.95,2887.83 501.95,2879.83 517.4,2879.83 536.14,2861.09 ; v1(493.95,2895.83) 479.95,2909.83 479.95,2950.91 508.13,2979.09 515.31,2979.09 ; U5101.33@494.3,1846.09 U5101.33@500.31,1840.08 ; 497.35,2790.37 SC9154.2@497.35,2810.09 497.35,2790.37 ; U5101.33@500.31,1840.08 U5101.33@507.3,1833.09 ; U5101.33@507.3,1833.09 U5101.33@512.31,1828.08 ; 536.14,2861.09 543.4,2853.83 595.31,2853.83 ; 536.14,2861.09 547.31,2872.26 547.31,2894.27 551.14,2898.09 583.59,2898.09 595.31,2886.37 595.31,2853.83 ; v1@563.98,2297.75 CON6102.15@582.62,2297.75 v1@563.98,2297.75 ; CON4001.15@587.41,907.56 CON4001.15@587.41,907.94 ; CON4001.15@587.41,907.56 CON4001.15@589.15,909.3 ; CON4001.15@587.41,907.56 CON4001.15@587.41,907.94 ; CON4001.15@587.41,907.56 CON4001.15@589.15,909.3 ; CON4001.15@587.41,907.94 v1(588.95,909.49) CON4001.15@589.34,909.49 ; CON4001.16@587.41,1470.55 CON4001.16@593.87,1477.01 ; CON4001.16@587.41,1470.55 CON4001.16@593.88,1477.01 ; CON4001.16@587.41,1470.55 601.16,1470.55 CON4001.16@608.1,1477.49 ; CON4001.15@589.15,909.3 CON4001.15@589.34,909.49 ; CON4001.15@589.15,909.3 CON4001.15@589.34,909.49 ; CON4001.16@593.87,1477.01 CON4001.16@594.35,1477.49 ; CON4001.16@593.88,1477.01 CON4001.16@594.35,1477.49 ; CON4001.16@594.35,1477.49 CON4001.16@608.1,1477.49 ; 595.31,2853.83 699.44,2853.83 713.2,2867.6 713.2,2868 721.29,2876.09 ; SC9139.5@611.31,4387.01 SC9139.5@614.61,4390.31 ; SC9139.5@611.31,4387.01 SC9139.5@614.61,4390.31 ; SC9139.5@611.31,4387.01 SC9139.5@614.62,4390.31 ; SC9154.4@625.21,2810.09 SC9154.4@627.27,2810.09 SC9154.4@627.28,2814.16 ; C5122.2@639.3,1784.09 v1(635.31,1788.09) C5122.2@639.3,1784.09 ; v1(649.54,2329.25) CON6102.18@649.54,2330.08 ; v1(649.54,2329.25) 649.74,2329.3 CON6102.18@649.54,2330.08 ; v1(649.54,2329.25) CON6102.18@649.54,2330.08 ; CON6102.21@649.55,2376.49 CON6102.21@649.54,2376.89 ; CON6102.21@649.55,2376.49 v1(649.95,2376.49) 649.74,2376.69 CON6102.21@649.54,2376.89 ; CON6102.21@649.55,2376.49 CON6102.21@649.54,2376.89 ; CON6102.27@649.55,2470.98 649.54,2471.08 v1(649.95,2471.49) CON6102.27@650.05,2471.49 ; CON6102.27@649.55,2470.98 CON6102.27@650.05,2471.49 ; CON6102.27@649.55,2470.98 650,2471.44 CON6102.27@650.05,2471.49 ; CON6102.24@649.7,2423.73 CON6102.24@649.55,2423.74 CON6102.24@649.7,2423.73 ; U5003.3@684.76,4482.74 684.95,4482.55 U5003.3@684.76,4482.74 ; SC9162.3@710.5,4287.49 SC9162.3@716.84,4293.83 ; SC9162.3@710.5,4287.49 SC9162.3@716.84,4293.83 ; C2033.2@743.95,3211.83 C2033.2@744.31,3211.47 ; F5001.3@745.38,4562.52 F5001.3@747.92,4562.52 ; F5001.3@745.38,4562.52 F5001.3@747.92,4562.52 ; F5001.1@745.38,4613.2 F5001.1@745.38,4613.7 ; F5001.1@745.38,4613.2 F5001.1@745.38,4613.7 ; F5001.7@798.16,4613.7 F5001.7@798.53,4613.7 F5001.7@798.16,4613.7 ; F5001.5@798.52,4561.35 F5001.5@798.53,4562.52 F5001.5@798.52,4562.91 ; F5001.5@798.52,4561.35 798.06,4562.28 v1(796.95,4564.49) F5001.5@798.52,4562.91 ; F5001.5@798.52,4561.35 F5001.5@798.52,4562.91 ; SC9162.1@829.4,4287.49 829.4,4288.3 SC9162.1@830.22,4288.3 ; SC9162.1@829.4,4287.49 SC9162.1@830.22,4288.3 ; SC9162.1@829.4,4287.49 SC9162.1@830.22,4288.3 ; SC9162.1@829.4,4287.49 SC9162.1@834.21,4288.3 ; SC9162.1@829.4,4287.49 SC9162.1@829.56,4287.52 ; SC9162.1@829.4,4287.49 SC9162.1@829.56,4287.52 ; SC9162.1@829.4,4287.49 SC9162.1@836.27,4288.3 ; SC9162.1@829.4,4287.49 SC9162.1@834.18,4288.3 ; SC9162.1@829.56,4287.52 SC9162.1@834.21,4288.3 ; SC9162.1@829.56,4287.52 SC9162.1@834.18,4288.3 ; SC9162.1@830.22,4288.3 832.54,4290.62 SC9162.1@847.85,4290.62 ; SC9162.1@830.22,4288.3 SC9162.1@834.18,4288.3 ; SC9162.1@834.18,4288.3 SC9162.1@847.85,4290.62 ; SC9162.1@834.18,4288.3 SC9162.1@847.85,4290.62 ; SC9162.1@834.21,4288.3 SC9162.1@836.27,4288.3 ; SC9162.1@836.27,4288.3 845.53,4288.3 SC9162.1@846.77,4289.54 ; SC9162.1@836.27,4288.3 SC9162.1@846.77,4289.54 ; SC9162.1@846.77,4289.54 855.93,4290.62 SC9162.1@847.85,4290.62 ; SC9162.1@846.77,4289.54 SC9162.1@847.85,4290.62 ; U5004.1@861.48,4496.36 U5004.1@864.86,4496.36 U5004.1@861.48,4496.36 ; U5001.1@912.88,4446.11 U5001.1@913.02,4445.98 ; U5001.1@912.88,4446.11 U5001.1@913.02,4445.98 ; U5001.1@913.02,4445.98 U5001.1@913.53,4446.49 ; U5001.1@913.02,4445.98 U5001.1@913.53,4446.49 ; U2001.J9@947.22,3132.49 U2001.J9@947.23,3132.36 ; U2001.J9@947.22,3132.49 U2001.J9@947.2,3132.83 ; U2001.J9@947.2,3132.48 U2001.J9@947.23,3132.36 ; U2001.J9@947.2,3132.48 U2001.J9@947.23,3132.36 ; U2001.J9@947.2,3132.48 947.16,3132.65 v4(947.08,3132.96) 947.15,3132.89 U2001.J9@947.2,3132.83 ; C10092.2@947.45,4208.83 946.2,4207.58 945.95,4207.58 C10092.2@945.95,4207.83 945.95,4208.83 C10092.2@947.45,4208.83 ; C10092.2@947.45,4208.83 947.7,4209.08 v1(947.95,4208.83) C10092.2@947.45,4208.83 ; U1001.B5@1002.31,3730.14 1002.31,3728.43 1006.63,3724.11 ; U1001.B5@1002.31,3730.14 U1001.B5@1002.35,3730.1 ; U1001.B5@1002.31,3730.14 1000.59,3730.14 v4(998.48,3732.26) 1003.25,3732.26 1005.88,3732.26 1006.88,3731.25 ; U1001.B5@1002.35,3730.1 1006.88,3730.1 ; U1001.B5@1002.35,3730.1 1005.47,3726.98 1009.5,3726.98 ; 1006.63,3724.11 1007.9,3724.11 1009.76,3725.97 ; 1006.63,3724.11 1009.5,3726.98 ; 1006.63,3724.11 1009.76,3720.98 1009.76,3725.97 ; 1006.88,3730.1 1006.88,3729.6 1009.5,3726.98 ; 1006.88,3730.1 1006.88,3731.25 ; 1006.88,3731.25 1009.5,3728.63 1009.5,3726.98 ; 1009.5,3726.98 1012.57,3730.05 1012.72,3730.05 ; 1009.76,3725.97 1013.28,3729.49 1013.84,3730.05 ; 1012.72,3730.05 1013.84,3730.05 ; 1012.72,3730.05 1012.72,3731.17 ; 1012.72,3731.17 1013.84,3730.05 ; v1(1018.95,4505.83) 1019.08,4505.7 1019.26,4505.52 L5010.2@1019.95,4504.83 ; v1(1018.95,4505.83) 1019.08,4505.83 1019.95,4505.83 L5010.2@1019.95,4504.83 ; v1(1018.95,4505.83) 1019.08,4505.61 L5010.2@1019.95,4504.11 ; L5010.2@1019.95,4504.11 1019.95,4503.98 L5010.2@1020.08,4504.11 ; L5010.2@1019.95,4504.11 1019.95,4504.32 L5010.2@1019.95,4504.83 ; L5010.2@1019.95,4504.83 L5010.2@1020.08,4504.11 ; L5010.2@1019.95,4504.83 L5010.2@1020.08,4504.7 ; L5010.2@1020.08,4504.11 L5010.2@1020.08,4504.7 ; U2001.D6@1025.82,3181.35 v4(1025.82,3180.2) U2001.D6@1025.82,3181.35 ; U5005.5@1086.86,4607.11 U5005.5@1087.24,4607.49 ; U5005.5@1086.86,4607.11 U5005.5@1087.24,4607.49 ; C2015.2@1089.45,3340.49 C2015.2@1089.82,3340.49 ; C2015.2@1089.82,3340.49 1089.82,3340.85 C2015.2@1090.18,3340.49 ; C2015.2@1089.82,3340.49 C2015.2@1090.18,3340.49 ; U1001.H17@1092.97,3921.24 U1001.H17@1092.95,3921.49 ; U1001.H17@1092.97,3921.24 U1001.H17@1092.95,3921.49 ; U1001.H17@1092.97,3921.24 U1001.H17@1092.97,3921.47 ; C2011.2@1112.95,3143.83 C2011.2@1112.95,3148.49 ; C2011.2@1112.95,3143.83 1112.95,3138.83 v1(1108.95,3138.83) 1109.66,3140.54 1111.31,3144.51 C2011.2@1112.95,3148.49 ; U5005.2@1120.95,4606.75 v1(1121.3,4607.11) U5005.2@1120.95,4606.75 ; C2013.2@1130.45,2982.19 C2013.2@1130.79,2981.57 ; C2013.2@1130.45,2982.19 v1(1129.02,2984.8) C2013.2@1130.79,2982.53 ; C2013.2@1130.45,2982.19 1130.31,2982.05 C2013.2@1130.79,2981.57 ; C2013.2@1130.45,2982.19 C2013.2@1130.79,2982.53 ; C2013.2@1130.79,2981.57 C2013.2@1130.79,2982.53 ; C2013.2@1130.79,2981.57 1130.79,2979.09 C2013.2@1132.31,2979.09 ; C2013.2@1130.79,2981.57 C2013.2@1131.55,2980.81 ; C2013.2@1130.79,2982.53 C2013.2@1131.55,2980.81 ; C2013.2@1131.55,2980.81 C2013.2@1132.31,2979.09 ; C2013.2@1131.55,2980.81 1132.79,2979.57 1132.31,2979.57 C2013.2@1132.31,2979.09 ; 1132.73,3755.49 v4(1124.46,3763.76) 1132.73,3755.49 ; SC9111.1@1174.43,4637.09 v1(1168.31,4637.09) 1167.31,4638.09 1173.43,4638.09 SC9111.1@1174.43,4637.09 ; 1183.95,3032.41 1184.94,3032.41 ; 1183.95,3032.41 v1@1183.96,3034.97 ; v1@1183.96,3034.97 1185.95,3032.97 ; v1@1183.96,3034.97 1184.94,3032.41 ; v1@1183.96,3034.97 1185.95,3032.97 ; v1@1183.96,3034.97 1183.96,3033.39 1184.94,3032.41 ; 1184.94,3032.41 1185.95,3032.41 1185.95,3032.97 ; v1@1215.17,3249.14 1218.34,3252.31 v1@1218.85,3252.83 ; v1@1215.17,3249.15 v1@1218.85,3252.83 ; 1218.95,3328.97 1219.07,3328.97 ; 1218.95,3328.97 v1@1218.95,3332.08 ; 1218.95,3328.97 1219.07,3328.97 ; 1218.95,3328.97 1219.07,3328.97 ; v1@1218.95,3332.08 v1(1220.95,3335.02) 1220.95,3328.97 ; v1@1218.95,3332.08 1219.07,3328.97 ; 1219.07,3328.97 1220.94,3328.97 ; 1219.07,3328.97 1220.95,3328.97 ; v1(1262.95,4179.83) 1261.95,4178.83 1262.95,4178.83 v1(1262.95,4179.83) ; U1001.W2@1266.13,3685.04 1266.19,3685.24 v4(1266.2,3685.02) U1001.W2@1266.13,3685.04 ; SC9102.3@1359.29,4338.83 1363.55,4343.09 1367.42,4340.44 SC9102.3@1368.49,4338.83 ; SC9102.3@1359.29,4338.83 SC9102.3@1368.49,4338.83 ; C10040.2@1428.92,3499.8 1430.61,3501.49 C10040.2@1433.54,3501.49 ; C10040.2@1428.92,3499.8 1429.26,3499.17 1429.95,3497.9 C10040.2@1433.54,3501.49 ; C10040.2@1428.92,3499.8 C10040.2@1433.54,3501.49 ; C10040.2@1433.54,3501.49 C10040.2@1436.01,3499.03 ; C10040.2@1433.54,3501.49 1436.01,3501.49 C10040.2@1436.01,3499.03 ; C10040.2@1433.54,3501.49 C10040.2@1436.01,3499.03 ; C10040.2@1436.01,3495.62 1436.2,3495.53 C10040.2@1442.95,3492.08 ; C10040.2@1436.01,3495.62 C10040.2@1436.01,3499.03 ; C10040.2@1436.01,3499.03 C10040.2@1442.95,3492.08 ; C10040.2@1436.01,3499.03 1437.94,3497.09 C10040.2@1442.95,3492.08 ; U1001.AK30@1441.31,4125.96 U1001.AK30@1439.43,4125.96 U1001.AK30@1441.31,4125.96 ; C10038.2@1458.4,3360.49 C10038.2@1458.4,3370.04 ; C10036.2@1458.4,3437.49 C10036.2@1458.4,3439.04 ; 1516.91,3086.09 1516.9,3088.09 ; 1516.91,3086.09 1516.91,3088.09 ; 1516.9,3088.09 1516.91,3088.68 ; 1516.91,3088.09 1516.91,3088.68 ; 1516.91,3138.09 v1@1519.31,3141.62 ; 1516.91,3138.09 1519.31,3140.5 v1@1519.31,3141.62 ; 1516.91,3138.11 1516.91,3139.5 ; 1516.91,3138.1 1516.96,3138.17 ; 1516.91,3138.09 1516.96,3138.17 ; 1516.91,3138.11 1518.11,3140.2 ; 1516.91,3138.11 1517.06,3138.35 ; 1516.91,3138.09 1516.96,3138.17 ; 1516.91,3138.11 v1@1518.98,3141.75 ; 1516.91,3138.09 1516.98,3138.2 ; 1516.9,3138.09 1512.95,3142.77 1509.31,3147.09 1512.95,3143.45 1516.91,3139.5 ; 1516.91,3138.11 1518.37,3141.14 ; 1516.91,3138.09 1516.96,3138.17 ; 1516.91,3138.1 1516.96,3138.17 ; 1516.91,3138.11 v1@1518.98,3141.75 ; 1516.91,3139.5 1516.91,3139.68 ; 1516.91,3139.68 1516.91,3140.68 v1@1519.31,3143.09 ; 1516.91,3139.68 1518.37,3141.14 ; 1516.96,3138.17 1517.07,3138.36 ; 1516.96,3138.17 1517.06,3138.35 ; 1516.96,3138.17 1517.06,3138.35 ; 1516.98,3138.2 v1@1519.31,3141.62 ; 1516.98,3138.2 v1@1519.31,3142.09 ; 1516.98,3138.2 v1@1519.31,3141.62 ; 1517.07,3138.36 v1@1519,3141.77 ; 1517.07,3138.36 v1@1519.31,3142.09 ; 1517.06,3138.35 1518.11,3140.2 ; 1517.06,3138.35 1518.31,3140.55 ; 1518.11,3140.2 1518.31,3140.55 ; 1518.11,3140.2 v1@1518.99,3141.75 ; 1518.31,3140.55 v1@1519,3141.77 ; 1518.31,3140.55 v1@1518.99,3141.76 ; 1518.37,3141.14 v1@1518.98,3141.75 ; 1518.37,3141.14 v1@1519.31,3143.09 ; v1@1518.99,3141.75 v1@1519.31,3142.33 ; v1@1518.98,3141.75 v1@1519.31,3142.33 ; v1@1518.99,3141.76 v1@1519.2,3142.13 ; v1@1518.98,3141.75 v1@1519.31,3142.33 ; v1@1519,3141.77 v1@1519.31,3142.09 ; v1@1519,3141.77 v1@1519.2,3142.13 ; v1@1519.2,3142.13 v1@1519.31,3142.33 ; v1@1519.2,3142.13 v1@1519.31,3142.33 ; v1@1519.31,3141.62 v1@1520.31,3143.09 ; v1@1519.31,3141.62 v1@1519.31,3142.09 ; v1@1519.31,3141.62 v1@1520.31,3143.09 ; v1@1519.31,3142.09 v1@1520.31,3143.09 ; v1@1519.31,3142.09 v1@1519.31,3142.33 ; v1@1519.31,3142.33 v1@1520.31,3144.09 ; v1@1519.31,3142.33 v1@1519.31,3143.09 ; v1@1519.31,3142.33 v1@1520.31,3144.09 ; v1@1519.31,3143.09 v1@1520.31,3144.09 ; v1@1520.31,3143.09 v1@1520.31,3144.09 ; v1@1520.31,3143.09 v1(1522.31,3146.09) ; v1@1520.31,3143.09 1524.31,3147.09 1523.31,3147.09 v1(1522.31,3146.09) ; v1@1520.31,3144.09 v1(1522.31,3146.09) ; v1(1548.95,4946.83) C6210.2@1552,4945.09 ; v1(1548.95,4946.83) C6210.2@1550.26,4946.83 ; v1(1548.95,4946.83) 1549.61,4947.49 C6210.2@1550.26,4946.83 ; C6210.2@1550.26,4946.83 C6210.2@1552,4945.09 ; C6210.2@1550.26,4946.83 1553.31,4946.83 C6210.2@1553.31,4945.09 1553.31,4944.43 1552.66,4944.43 C6210.2@1552,4945.09 ; SC9159.4@1619.95,3714.09 SC9159.4@1630.88,3725.02 ; SC9159.4@1619.95,3714.09 SC9159.4@1625.49,3725.56 ; SC9159.4@1619.95,3714.09 SC9159.4@1625.49,3725.56 ; SC9159.4@1625.49,3725.56 SC9159.4@1630.31,3735.53 ; SC9159.4@1625.49,3725.56 SC9159.4@1630.31,3735.53 ; SC9112.2@1626.31,3372.05 SC9112.2@1630.31,3376.05 SC9112.2@1626.31,3372.05 ; SC9159.4@1630.31,3735.53 SC9159.4@1630.8,3726.48 ; SC9159.4@1630.31,3735.53 1630.86,3726.53 1630.95,3725.09 SC9159.4@1630.88,3725.02 ; SC9159.4@1630.31,3735.53 SC9159.4@1630.8,3726.48 ; SC9159.2@1630.31,3865.45 1628.26,3866.05 SC9159.2@1630.31,3865.45 ; SC9159.4@1630.8,3726.48 SC9159.4@1630.88,3725.02 ; SC9159.4@1630.8,3726.48 SC9159.4@1630.88,3725.02 ; SC9159.4@1630.88,3725.02 SC9159.4@1630.95,3723.71 ; SC9159.4@1630.88,3725.02 SC9159.4@1630.95,3723.71 ; CON6202.30@1665.31,5059.09 v1(1666.31,5078.09) 1665.71,5059.49 1665.71,5058.69 CON6202.30@1665.31,5059.09 ; SC9136.1@1675.95,3946.83 1675.95,3944.83 SC9136.1@1676.55,3944.23 ; SC9136.1@1675.95,3946.83 1681.31,3941.47 SC9136.1@1681.31,3939.47 ; SC9136.1@1675.95,3946.83 SC9136.1@1676.55,3944.23 ; SC9136.1@1676.55,3944.23 SC9136.1@1681.31,3923.54 SC9136.1@1681.31,3939.47 ; SC9136.1@1676.55,3944.23 SC9136.1@1681.31,3939.47 ; SC9138.1@1681.43,3238.56 SC9138.1@1682.95,3237.04 SC9138.1@1681.43,3238.56 ; SC9119.2@1778.35,3280.56 SC9119.2@1789.35,3291.56 ; SC9119.2@1778.35,3280.56 SC9119.2@1789.35,3291.56 ; SC9103.2@1778.46,3334.56 SC9103.2@1779.53,3333.49 ; SC9103.2@1778.46,3334.56 SC9103.2@1778.46,3334.78 ; SC9103.2@1778.46,3334.78 1751.84,3334.78 1759.34,3342.29 1772.39,3342.29 1778.46,3336.22 SC9103.2@1778.46,3334.78 ; SC9103.2@1778.46,3334.78 1779.53,3334.78 SC9103.2@1779.53,3333.49 ; X3701.2@1794.45,4657.95 X3701.2@1794.46,4642.18 1794.46,4648.09 X3701.2@1794.45,4657.95 ; U3901.A2@1886.08,2808.59 v4(1886.43,2808.94) ; U3901.A2@1886.08,2808.59 1886.49,2808.84 v4(1886.43,2808.94) ; U3901.A2@1886.08,2808.59 v4(1886.43,2808.94) ; DPX3802.2@2011.61,4659.18 DPX3802.2@2012.95,4659.18 ; DPX3802.2@2011.61,4659.18 DPX3802.2@2012.95,4659.18 ; DPX3802.2@2012.95,4659.18 DPX3802.2@2015.23,4659.18 ; DPX3802.2@2012.95,4659.18 DPX3802.2@2015.23,4659.18 ; DPX3802.5@2044.35,4707.8 DPX3802.5@2045.14,4707.8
